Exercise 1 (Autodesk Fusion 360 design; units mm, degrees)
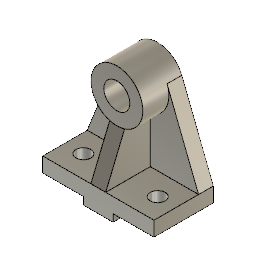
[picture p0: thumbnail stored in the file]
sketch "Sketch1" plane through (0, 0, 0) normal (0, 1, 0) x axis (1, 0, 0)
  line L1 (0, -28.6527) -> (0, 0)
  line L2 (-75, -10) -> (75, -10)
  line L3 (-75, 10) -> (-75, -10)
  line L4 (75, -10) -> (75, 10)
  line L5 (-75, 10) -> (75, -10)
  line L6 (75, 10) -> (-75, -10)
  line L7 (-20, 20) -> (-20, 10)
  line L8 (20, 20) -> (-20, 20)
  line L9 (20, 10) -> (20, 20)
  line L10 (-20, 10) -> (-75, 10)
  line L11 (75, 10) -> (20, 10)
  point P1 (0, 0)
  point P2 (0, 0)
  point P8 (0, 0)
  point P12 (20, 10)
  point P5 (-75, -10)
  point P6 (-75, 10)
  point P10 (-20, 20)
  point P11 (20, 20)
  coincident P1 P2
  vertical L1
  horizontal L2
  perpendicular L2 L3
  parallel L2 L10
  parallel L3 L4
  coincident L5 P8
  coincident L6 P8
  coincident P1 P8
  perpendicular L7 L10
  perpendicular L7 L8
  coincident P12 L10
  perpendicular L9 L10
  collinear L10 L11
  dimension "d1" distance L3 L4 = 150
  dimension "d2" distance P5 P6 = 20
  dimension "d3" distance P10 P11 = 40
  dimension "d4" distance P11 P12 = 10
extrude "Extrude1" new body sketch "Sketch1" profile of L2 L3 L11 L4 L7 L8 L9 along normal blind 80
sketch "Sketch2" plane through (0, 80, 0) normal (0, 1, 0) x axis (-1, 0, 0)
  line L1 (-20, -20) -> (-20, -10)
  line L2 (20, -20) -> (-20, -20)
  line L3 (20, -10) -> (20, -20)
  line L4 (75, -10) -> (20, -10)
  line L5 (75, 10) -> (75, -10)
  line L6 (-75, 10) -> (75, 10)
  line L7 (-75, -10) -> (-75, 10)
  line L8 (-20, -10) -> (-75, -10)
  line L9 (-32.5686, 117.8173) -> (-75, 10)
  line L10 (75, 10) -> (32.5686, 117.8173)
  line L11 (75, 10) -> (-75, 10)
  line L12 (0, 54.3936) -> (0, 0)
  arc A1 centre (0, 105) radius 35 clockwise from (-32.5686, 117.8173) to (32.5686, 117.8173)
  point P8 (-75, 10)
  point P10 (-75, 10)
  point P7 (75, 10)
  point P14 (75, 10)
  point P15 (-75, 10)
  point P16 (75, 10)
  point P1 (0, 0)
  point P17 (0, 0)
  point P13 (0, 105)
  coincident P8 P10
  tangent L9 A1
  coincident P7 P14
  coincident P8 P15
  coincident P7 P16
  coincident P1 P17
  perpendicular L6 L12
  coincident P13 L12
  tangent A1 L10
  dimension "d7" distance P13 L11 = 95
  dimension "d8" radius A1 = 35
extrude "Extrude2" add sketch "Sketch2" profile of L6 L9 A1 L10 L11 against normal blind 20
sketch "Sketch3" plane through (0, 60, 0) normal (0, -1, 0) x axis (1, 0, 0)
  line L1 (-75, 10) -> (-32.5686, 117.8173)
  line L2 (75, 10) -> (-75, 10)
  line L3 (32.5686, 117.8173) -> (75, 10)
  arc A1 centre (0, 105) radius 35 clockwise from (-32.5686, 117.8173) to (32.5686, 117.8173)
  circle C1 centre (0, 105) radius 35
  concentric A1 C1
  dimension "d11" diameter C1 = 70
extrude "Extrude3" add sketch "Sketch3" profile of A1 C1 along normal blind 35
sketch "Sketch4" plane through (0, 25, 0) normal (0, -1, 0) x axis (1, 0, 0)
  circle C1 centre (0, 105) radius 35
  circle C2 centre (0, 105) radius 17.5
  concentric C1 C2
  dimension "d14" diameter C2 = 35
extrude "Extrude4" cut sketch "Sketch4" profile of C2 no distance stored
sketch "Sketch5" plane through (0, 0, 10) normal (0, 0, 1) x axis (-1, 0, 0)
  line L1 (75, -60) -> (-75, -60)
  line L2 (75, 0) -> (75, -60)
  line L3 (-75, 0) -> (75, 0)
  line L4 (-75, -60) -> (-75, 0)
  circle C1 centre (50, -30) radius 10
  point P6 (50, -30)
  dimension "d16" diameter C1 = 20
  dimension "d17" distance L3 P6 = 30
  dimension "d18" distance L2 P6 = 25
extrude "Extrude5" cut sketch "Sketch5" profile of C1 no distance stored
mirror "Mirror1"
sketch "Sketch6" plane through (0, 0, 0) normal (1, 0, 0) x axis (0, 1, 0)
  line L1 (25, 70) -> (25, 140)
  line L2 (0, 10) -> (25, 70.1191)
  point P5 (25, 70.1191)
  point P4 (0, 10)
  point P6 (0, 10)
  coincident L1 P5
  coincident P4 P6
step "Rib" Thickness 20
